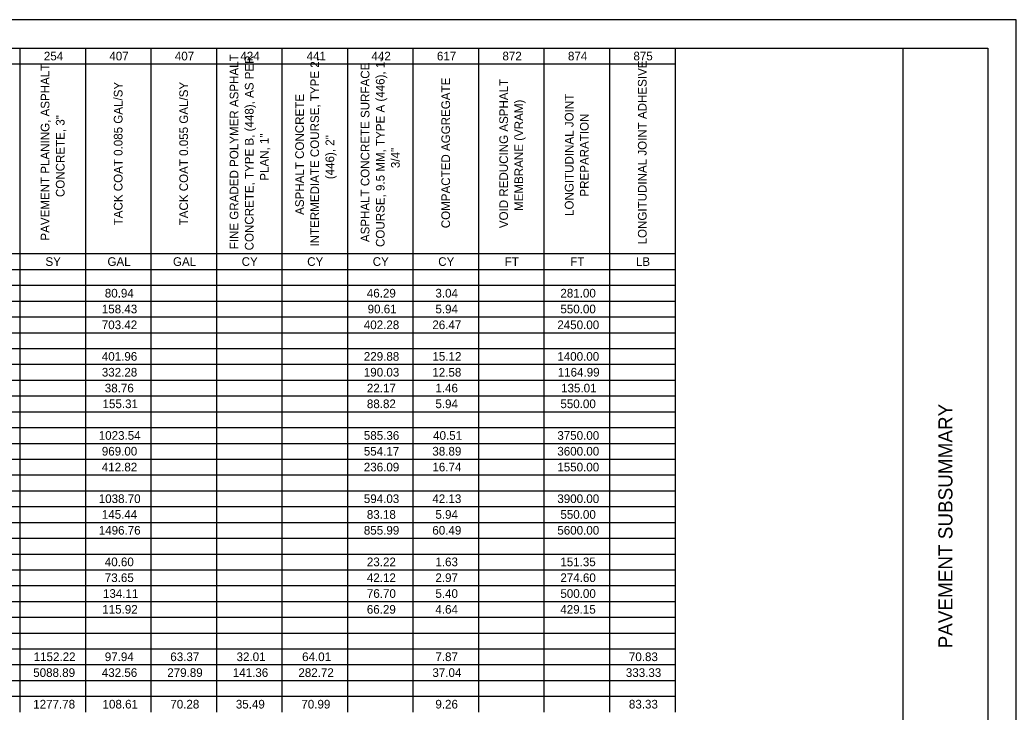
# Model space of a CAD drawing. Extents: x 0 to 34.4, y 0 to 47.
# Drawn here: x 16.38 to 34, y 9.75 to 22 of the extents above; entities that cross this region are included whole.
import ezdxf

# ---------------------------------------------------------------- set-up
doc = ezdxf.new("R2010")
doc.units = 0
for name, color, linetype in [('SH_Border', 7, 'Continuous'), ('SH_Cut_Line', 7, 'Continuous'), ('SH_Data', 7, 'Continuous'), ('SH_Text', 7, 'Continuous')]:
    doc.layers.add(name, color=color, linetype=linetype)

msp = doc.modelspace()

# ---------------------------------------------------------------- linework, layer by layer
at = {"layer": 'SH_Border'}
msp.add_line((32, 0.5), (32, 21.5), dxfattribs=at)
msp.add_lwpolyline([(1.5, 21.5), (33.5, 21.5), (33.5, 0.5), (1.5, 0.5)], close=True, dxfattribs=at)
at = {"layer": 'SH_Cut_Line'}
msp.add_lwpolyline([(0, 0), (34, 0), (34, 22), (0, 22)], close=True, dxfattribs=at)
at = {"layer": 'SH_Text'}
for p, q in [((15.22, 21.5), (16.378, 21.5)), ((16.378, 21.5), (24.49, 21.5)), ((16.378, 21.5), (16.378, 21.22)), ((17.537, 21.5), (17.537, 21.22)), ((18.696, 21.5), (18.696, 21.22)), ((19.855, 21.5), (19.855, 21.22)), ((21.014, 21.5), (21.014, 21.22)), ((22.173, 21.5), (22.173, 21.22)), ((23.331, 21.5), (23.331, 21.22)), ((24.49, 21.5), (25.649, 21.5)), ((24.49, 21.5), (24.49, 21.22)), ((25.649, 21.5), (27.967, 21.5)), ((25.649, 21.5), (25.649, 21.22)), ((26.808, 21.5), (26.808, 21.22)), ((27.967, 21.5), (27.967, 21.22)), ((15.22, 21.22), (16.378, 21.22)), ((16.378, 21.22), (24.49, 21.22)), ((16.378, 21.22), (16.378, 20.941)), ((17.537, 21.22), (17.537, 20.941)), ((18.696, 21.22), (18.696, 20.941)), ((19.855, 21.22), (19.855, 20.941)), ((21.014, 21.22), (21.014, 20.941)), ((22.173, 21.22), (22.173, 20.941)), ((23.331, 21.22), (23.331, 20.941)), ((24.49, 21.22), (25.649, 21.22)), ((24.49, 21.22), (24.49, 20.941)), ((25.649, 21.22), (27.967, 21.22)), ((25.649, 21.22), (25.649, 20.941)), ((26.808, 21.22), (26.808, 20.941)), ((27.967, 21.22), (27.967, 20.941)), ((16.378, 20.941), (16.378, 20.661)), ((17.537, 20.941), (17.537, 20.661)), ((18.696, 20.941), (18.696, 20.661)), ((19.855, 20.941), (19.855, 20.661)), ((21.014, 20.941), (21.014, 20.661)), ((22.173, 20.941), (22.173, 20.661)), ((23.331, 20.941), (23.331, 20.661)), ((24.49, 20.941), (24.49, 20.661)), ((25.649, 20.941), (25.649, 20.661)), ((26.808, 20.941), (26.808, 20.661)), ((27.967, 20.941), (27.967, 20.661)), ((16.378, 20.661), (16.378, 20.101)), ((17.537, 20.661), (17.537, 20.101)), ((18.696, 20.661), (18.696, 20.101)), ((19.855, 20.661), (19.855, 20.101)), ((21.014, 20.661), (21.014, 20.101)), ((22.173, 20.661), (22.173, 20.101)), ((23.331, 20.661), (23.331, 20.101)), ((24.49, 20.661), (24.49, 20.101)), ((25.649, 20.661), (25.649, 20.101)), ((26.808, 20.661), (26.808, 20.101)), ((27.967, 20.661), (27.967, 20.101)), ((16.378, 20.101), (16.378, 19.822)), ((17.537, 20.101), (17.537, 19.822)), ((18.696, 20.101), (18.696, 19.822)), ((19.855, 20.101), (19.855, 19.822)), ((21.014, 20.101), (21.014, 19.822)), ((22.173, 20.101), (22.173, 19.822)), ((23.331, 20.101), (23.331, 19.822)), ((24.49, 20.101), (24.49, 19.822)), ((25.649, 20.101), (25.649, 19.822)), ((26.808, 20.101), (26.808, 19.822)), ((27.967, 20.101), (27.967, 19.822)), ((16.378, 19.822), (16.378, 19.542)), ((17.537, 19.822), (17.537, 19.542)), ((18.696, 19.822), (18.696, 19.542)), ((19.855, 19.822), (19.855, 19.542)), ((21.014, 19.822), (21.014, 19.542)), ((22.173, 19.822), (22.173, 19.542)), ((23.331, 19.822), (23.331, 19.542)), ((24.49, 19.822), (24.49, 19.542)), ((25.649, 19.822), (25.649, 19.542)), ((26.808, 19.822), (26.808, 19.542)), ((27.967, 19.822), (27.967, 19.542)), ((16.378, 19.542), (16.378, 19.262)), ((17.537, 19.542), (17.537, 19.262)), ((18.696, 19.542), (18.696, 19.262)), ((19.855, 19.542), (19.855, 19.262)), ((21.014, 19.542), (21.014, 19.262)), ((22.173, 19.542), (22.173, 19.262)), ((23.331, 19.542), (23.331, 19.262)), ((24.49, 19.542), (24.49, 19.262)), ((25.649, 19.542), (25.649, 19.262)), ((26.808, 19.542), (26.808, 19.262)), ((27.967, 19.542), (27.967, 19.262)), ((16.378, 19.262), (16.378, 18.983)), ((17.537, 19.262), (17.537, 18.983)), ((18.696, 19.262), (18.696, 18.983)), ((19.855, 19.262), (19.855, 18.983)), ((21.014, 19.262), (21.014, 18.983)), ((22.173, 19.262), (22.173, 18.983)), ((23.331, 19.262), (23.331, 18.983)), ((24.49, 19.262), (24.49, 18.983)), ((25.649, 19.262), (25.649, 18.983)), ((26.808, 19.262), (26.808, 18.983)), ((27.967, 19.262), (27.967, 18.983)), ((16.378, 18.983), (16.378, 18.703)), ((17.537, 18.983), (17.537, 18.703)), ((18.696, 18.983), (18.696, 18.703)), ((19.855, 18.983), (19.855, 18.703)), ((21.014, 18.983), (21.014, 18.703)), ((22.173, 18.983), (22.173, 18.703)), ((23.331, 18.983), (23.331, 18.703)), ((24.49, 18.983), (24.49, 18.703)), ((25.649, 18.983), (25.649, 18.703)), ((26.808, 18.983), (26.808, 18.703)), ((27.967, 18.983), (27.967, 18.703)), ((16.378, 18.703), (16.378, 18.423)), ((17.537, 18.703), (17.537, 18.423)), ((18.696, 18.703), (18.696, 18.423)), ((19.855, 18.703), (19.855, 18.423)), ((21.014, 18.703), (21.014, 18.423)), ((22.173, 18.703), (22.173, 18.423)), ((23.331, 18.703), (23.331, 18.423)), ((24.49, 18.703), (24.49, 18.423)), ((25.649, 18.703), (25.649, 18.423)), ((26.808, 18.703), (26.808, 18.423)), ((27.967, 18.703), (27.967, 18.423)), ((16.378, 18.423), (16.378, 18.143)), ((17.537, 18.423), (17.537, 18.143)), ((18.696, 18.423), (18.696, 18.143)), ((19.855, 18.423), (19.855, 18.143)), ((21.014, 18.423), (21.014, 18.143)), ((22.173, 18.423), (22.173, 18.143)), ((23.331, 18.423), (23.331, 18.143)), ((24.49, 18.423), (24.49, 18.143)), ((25.649, 18.423), (25.649, 18.143)), ((26.808, 18.423), (26.808, 18.143)), ((27.967, 18.423), (27.967, 18.143)), ((16.378, 18.143), (16.378, 17.864)), ((17.537, 18.143), (17.537, 17.864)), ((18.696, 18.143), (18.696, 17.864)), ((19.855, 18.143), (19.855, 17.864)), ((21.014, 18.143), (21.014, 17.864)), ((22.173, 18.143), (22.173, 17.864)), ((23.331, 18.143), (23.331, 17.864)), ((24.49, 18.143), (24.49, 17.864)), ((25.649, 18.143), (25.649, 17.864)), ((26.808, 18.143), (26.808, 17.864)), ((27.967, 18.143), (27.967, 17.864)), ((15.22, 17.864), (16.378, 17.864)), ((16.378, 17.864), (24.49, 17.864)), ((16.378, 17.864), (16.378, 17.584)), ((17.537, 17.864), (17.537, 17.584)), ((18.696, 17.864), (18.696, 17.584)), ((19.855, 17.864), (19.855, 17.584)), ((21.014, 17.864), (21.014, 17.584)), ((22.173, 17.864), (22.173, 17.584)), ((23.331, 17.864), (23.331, 17.584)), ((24.49, 17.864), (25.649, 17.864)), ((24.49, 17.864), (24.49, 17.584)), ((25.649, 17.864), (27.967, 17.864)), ((25.649, 17.864), (25.649, 17.584)), ((26.808, 17.864), (26.808, 17.584)), ((27.967, 17.864), (27.967, 17.584)), ((15.22, 17.584), (16.378, 17.584)), ((16.378, 17.584), (24.49, 17.584)), ((16.378, 17.584), (16.378, 17.304)), ((17.537, 17.584), (17.537, 17.304)), ((18.696, 17.584), (18.696, 17.304)), ((19.855, 17.584), (19.855, 17.304)), ((21.014, 17.584), (21.014, 17.304)), ((22.173, 17.584), (22.173, 17.304)), ((23.331, 17.584), (23.331, 17.304)), ((24.49, 17.584), (25.649, 17.584)), ((24.49, 17.584), (24.49, 17.304)), ((25.649, 17.584), (27.967, 17.584)), ((25.649, 17.584), (25.649, 17.304)), ((26.808, 17.584), (26.808, 17.304)), ((27.967, 17.584), (27.967, 17.304)), ((15.22, 17.304), (16.378, 17.304)), ((16.378, 17.304), (24.49, 17.304)), ((16.378, 17.304), (16.378, 17.024)), ((17.537, 17.304), (17.537, 17.024)), ((18.696, 17.304), (18.696, 17.024)), ((19.855, 17.304), (19.855, 17.024)), ((21.014, 17.304), (21.014, 17.024)), ((22.173, 17.304), (22.173, 17.024)), ((23.331, 17.304), (23.331, 17.024)), ((24.49, 17.304), (25.649, 17.304)), ((24.49, 17.304), (24.49, 17.024)), ((25.649, 17.304), (27.967, 17.304)), ((25.649, 17.304), (25.649, 17.024)), ((26.808, 17.304), (26.808, 17.024)), ((27.967, 17.304), (27.967, 17.024)), ((15.22, 17.024), (16.378, 17.024)), ((16.378, 17.024), (24.49, 17.024)), ((16.378, 17.024), (16.378, 16.745)), ((17.537, 17.024), (17.537, 16.745)), ((18.696, 17.024), (18.696, 16.745)), ((19.855, 17.024), (19.855, 16.745)), ((21.014, 17.024), (21.014, 16.745)), ((22.173, 17.024), (22.173, 16.745)), ((23.331, 17.024), (23.331, 16.745)), ((24.49, 17.024), (25.649, 17.024)), ((24.49, 17.024), (24.49, 16.745)), ((25.649, 17.024), (27.967, 17.024)), ((25.649, 17.024), (25.649, 16.745)), ((26.808, 17.024), (26.808, 16.745)), ((27.967, 17.024), (27.967, 16.745)), ((15.22, 16.745), (16.378, 16.745)), ((16.378, 16.745), (24.49, 16.745)), ((16.378, 16.745), (16.378, 16.185)), ((17.537, 16.745), (17.537, 16.185)), ((18.696, 16.745), (18.696, 16.185)), ((19.855, 16.745), (19.855, 16.185)), ((21.014, 16.745), (21.014, 16.185)), ((22.173, 16.745), (22.173, 16.185)), ((23.331, 16.745), (23.331, 16.185)), ((24.49, 16.745), (25.649, 16.745)), ((24.49, 16.745), (24.49, 16.185)), ((25.649, 16.745), (27.967, 16.745)), ((25.649, 16.745), (25.649, 16.185)), ((26.808, 16.745), (26.808, 16.185)), ((27.967, 16.745), (27.967, 16.185)), ((15.22, 16.465), (16.378, 16.465)), ((16.378, 16.465), (24.49, 16.465)), ((24.49, 16.465), (25.649, 16.465)), ((25.649, 16.465), (27.967, 16.465)), ((15.22, 16.185), (16.378, 16.185)), ((16.378, 16.185), (24.49, 16.185)), ((16.378, 16.185), (16.378, 15.906)), ((17.537, 16.185), (17.537, 15.906)), ((18.696, 16.185), (18.696, 15.906)), ((19.855, 16.185), (19.855, 15.906)), ((21.014, 16.185), (21.014, 15.906)), ((22.173, 16.185), (22.173, 15.906)), ((23.331, 16.185), (23.331, 15.906)), ((24.49, 16.185), (25.649, 16.185)), ((24.49, 16.185), (24.49, 15.906)), ((25.649, 16.185), (27.967, 16.185)), ((25.649, 16.185), (25.649, 15.906)), ((26.808, 16.185), (26.808, 15.906)), ((27.967, 16.185), (27.967, 15.906)), ((15.22, 15.906), (16.378, 15.906)), ((16.378, 15.906), (24.49, 15.906)), ((16.378, 15.906), (16.378, 15.626)), ((17.537, 15.906), (17.537, 15.626)), ((18.696, 15.906), (18.696, 15.626)), ((19.855, 15.906), (19.855, 15.626)), ((21.014, 15.906), (21.014, 15.626)), ((22.173, 15.906), (22.173, 15.626)), ((23.331, 15.906), (23.331, 15.626)), ((24.49, 15.906), (25.649, 15.906)), ((24.49, 15.906), (24.49, 15.626)), ((25.649, 15.906), (27.967, 15.906)), ((25.649, 15.906), (25.649, 15.626)), ((26.808, 15.906), (26.808, 15.626)), ((27.967, 15.906), (27.967, 15.626)), ((15.22, 15.626), (16.378, 15.626)), ((16.378, 15.626), (24.49, 15.626)), ((16.378, 15.626), (16.378, 15.346)), ((17.537, 15.626), (17.537, 15.346)), ((18.696, 15.626), (18.696, 15.346)), ((19.855, 15.626), (19.855, 15.346)), ((21.014, 15.626), (21.014, 15.346)), ((22.173, 15.626), (22.173, 15.346)), ((23.331, 15.626), (23.331, 15.346)), ((24.49, 15.626), (25.649, 15.626)), ((24.49, 15.626), (24.49, 15.346)), ((25.649, 15.626), (27.967, 15.626)), ((25.649, 15.626), (25.649, 15.346)), ((26.808, 15.626), (26.808, 15.346)), ((27.967, 15.626), (27.967, 15.346)), ((15.22, 15.346), (16.378, 15.346)), ((16.378, 15.346), (24.49, 15.346)), ((16.378, 15.346), (16.378, 14.787)), ((17.537, 15.346), (17.537, 14.787)), ((18.696, 15.346), (18.696, 14.787)), ((19.855, 15.346), (19.855, 14.787)), ((21.014, 15.346), (21.014, 14.787)), ((22.173, 15.346), (22.173, 14.787)), ((23.331, 15.346), (23.331, 14.787)), ((24.49, 15.346), (25.649, 15.346)), ((24.49, 15.346), (24.49, 14.787)), ((25.649, 15.346), (27.967, 15.346)), ((25.649, 15.346), (25.649, 14.787)), ((26.808, 15.346), (26.808, 14.787)), ((27.967, 15.346), (27.967, 14.787)), ((15.22, 15.066), (16.378, 15.066)), ((16.378, 15.066), (24.49, 15.066)), ((24.49, 15.066), (25.649, 15.066)), ((25.649, 15.066), (27.967, 15.066)), ((15.22, 14.787), (16.378, 14.787)), ((16.378, 14.787), (24.49, 14.787)), ((16.378, 14.787), (16.378, 14.507)), ((17.537, 14.787), (17.537, 14.507)), ((18.696, 14.787), (18.696, 14.507)), ((19.855, 14.787), (19.855, 14.507)), ((21.014, 14.787), (21.014, 14.507)), ((22.173, 14.787), (22.173, 14.507)), ((23.331, 14.787), (23.331, 14.507)), ((24.49, 14.787), (25.649, 14.787)), ((24.49, 14.787), (24.49, 14.507)), ((25.649, 14.787), (27.967, 14.787)), ((25.649, 14.787), (25.649, 14.507)), ((26.808, 14.787), (26.808, 14.507)), ((27.967, 14.787), (27.967, 14.507)), ((15.22, 14.507), (16.378, 14.507)), ((16.378, 14.507), (24.49, 14.507)), ((16.378, 14.507), (16.378, 14.227)), ((17.537, 14.507), (17.537, 14.227)), ((18.696, 14.507), (18.696, 14.227)), ((19.855, 14.507), (19.855, 14.227)), ((21.014, 14.507), (21.014, 14.227)), ((22.173, 14.507), (22.173, 14.227)), ((23.331, 14.507), (23.331, 14.227)), ((24.49, 14.507), (25.649, 14.507)), ((24.49, 14.507), (24.49, 14.227)), ((25.649, 14.507), (27.967, 14.507)), ((25.649, 14.507), (25.649, 14.227)), ((26.808, 14.507), (26.808, 14.227)), ((27.967, 14.507), (27.967, 14.227)), ((15.22, 14.227), (16.378, 14.227)), ((16.378, 14.227), (24.49, 14.227)), ((16.378, 14.227), (16.378, 13.948)), ((17.537, 14.227), (17.537, 13.948)), ((18.696, 14.227), (18.696, 13.948)), ((19.855, 14.227), (19.855, 13.948)), ((21.014, 14.227), (21.014, 13.948)), ((22.173, 14.227), (22.173, 13.948)), ((23.331, 14.227), (23.331, 13.948)), ((24.49, 14.227), (25.649, 14.227)), ((24.49, 14.227), (24.49, 13.948)), ((25.649, 14.227), (27.967, 14.227)), ((25.649, 14.227), (25.649, 13.948)), ((26.808, 14.227), (26.808, 13.948)), ((27.967, 14.227), (27.967, 13.948)), ((15.22, 13.948), (16.378, 13.948)), ((16.378, 13.948), (24.49, 13.948)), ((16.378, 13.948), (16.378, 13.108)), ((17.537, 13.948), (17.537, 13.108)), ((18.696, 13.948), (18.696, 13.108)), ((19.855, 13.948), (19.855, 13.108)), ((21.014, 13.948), (21.014, 13.108)), ((22.173, 13.948), (22.173, 13.108)), ((23.331, 13.948), (23.331, 13.108)), ((24.49, 13.948), (25.649, 13.948)), ((24.49, 13.948), (24.49, 13.108)), ((25.649, 13.948), (27.967, 13.948)), ((25.649, 13.948), (25.649, 13.108)), ((26.808, 13.948), (26.808, 13.108)), ((27.967, 13.948), (27.967, 13.108)), ((15.22, 13.668), (16.378, 13.668)), ((16.378, 13.668), (24.49, 13.668)), ((24.49, 13.668), (25.649, 13.668)), ((25.649, 13.668), (27.967, 13.668)), ((15.22, 13.388), (16.378, 13.388)), ((16.378, 13.388), (24.49, 13.388)), ((24.49, 13.388), (25.649, 13.388)), ((25.649, 13.388), (27.967, 13.388)), ((15.22, 13.108), (16.378, 13.108)), ((16.378, 13.108), (24.49, 13.108)), ((16.378, 13.108), (16.378, 12.829)), ((17.537, 13.108), (17.537, 12.829)), ((18.696, 13.108), (18.696, 12.829)), ((19.855, 13.108), (19.855, 12.829)), ((21.014, 13.108), (21.014, 12.829)), ((22.173, 13.108), (22.173, 12.829)), ((23.331, 13.108), (23.331, 12.829)), ((24.49, 13.108), (25.649, 13.108)), ((24.49, 13.108), (24.49, 12.829)), ((25.649, 13.108), (27.967, 13.108)), ((25.649, 13.108), (25.649, 12.829)), ((26.808, 13.108), (26.808, 12.829)), ((27.967, 13.108), (27.967, 12.829)), ((15.22, 12.829), (16.378, 12.829)), ((16.378, 12.829), (24.49, 12.829)), ((16.378, 12.829), (16.378, 11.71)), ((17.537, 12.829), (17.537, 11.71)), ((18.696, 12.829), (18.696, 11.71)), ((19.855, 12.829), (19.855, 11.71)), ((21.014, 12.829), (21.014, 11.71)), ((22.173, 12.829), (22.173, 11.71)), ((23.331, 12.829), (23.331, 11.71)), ((24.49, 12.829), (25.649, 12.829)), ((24.49, 12.829), (24.49, 11.71)), ((25.649, 12.829), (27.967, 12.829)), ((25.649, 12.829), (25.649, 11.71)), ((26.808, 12.829), (26.808, 11.71)), ((27.967, 12.829), (27.967, 11.71)), ((15.22, 12.549), (16.378, 12.549)), ((16.378, 12.549), (24.49, 12.549)), ((24.49, 12.549), (25.649, 12.549)), ((25.649, 12.549), (27.967, 12.549)), ((15.22, 12.269), (16.378, 12.269)), ((16.378, 12.269), (24.49, 12.269)), ((24.49, 12.269), (25.649, 12.269)), ((25.649, 12.269), (27.967, 12.269)), ((15.22, 11.99), (16.378, 11.99)), ((16.378, 11.99), (24.49, 11.99)), ((24.49, 11.99), (25.649, 11.99)), ((25.649, 11.99), (27.967, 11.99)), ((15.22, 11.71), (16.378, 11.71)), ((16.378, 11.71), (24.49, 11.71)), ((16.378, 11.71), (16.378, 11.43)), ((17.537, 11.71), (17.537, 11.43)), ((18.696, 11.71), (18.696, 11.43)), ((19.855, 11.71), (19.855, 11.43)), ((21.014, 11.71), (21.014, 11.43)), ((22.173, 11.71), (22.173, 11.43)), ((23.331, 11.71), (23.331, 11.43)), ((24.49, 11.71), (25.649, 11.71)), ((24.49, 11.71), (24.49, 11.43)), ((25.649, 11.71), (27.967, 11.71)), ((25.649, 11.71), (25.649, 11.43)), ((26.808, 11.71), (26.808, 11.43)), ((27.967, 11.71), (27.967, 11.43)), ((15.22, 11.43), (16.378, 11.43)), ((16.378, 11.43), (24.49, 11.43)), ((16.378, 11.43), (16.378, 10.311)), ((17.537, 11.43), (17.537, 10.311)), ((18.696, 11.43), (18.696, 10.311)), ((19.855, 11.43), (19.855, 10.311)), ((21.014, 11.43), (21.014, 10.311)), ((22.173, 11.43), (22.173, 10.311)), ((23.331, 11.43), (23.331, 10.311)), ((24.49, 11.43), (25.649, 11.43)), ((24.49, 11.43), (24.49, 10.311)), ((25.649, 11.43), (27.967, 11.43)), ((25.649, 11.43), (25.649, 10.311)), ((26.808, 11.43), (26.808, 10.311)), ((27.967, 11.43), (27.967, 10.311)), ((15.22, 11.15), (16.378, 11.15)), ((16.378, 11.15), (24.49, 11.15)), ((24.49, 11.15), (25.649, 11.15)), ((25.649, 11.15), (27.967, 11.15)), ((15.22, 10.871), (16.378, 10.871)), ((16.378, 10.871), (24.49, 10.871)), ((24.49, 10.871), (25.649, 10.871)), ((25.649, 10.871), (27.967, 10.871)), ((15.22, 10.591), (16.378, 10.591)), ((16.378, 10.591), (24.49, 10.591)), ((24.49, 10.591), (25.649, 10.591)), ((25.649, 10.591), (27.967, 10.591)), ((15.22, 10.311), (16.378, 10.311)), ((16.378, 10.311), (24.49, 10.311)), ((16.378, 10.311), (16.378, 9.752)), ((17.537, 10.311), (17.537, 9.752)), ((18.696, 10.311), (18.696, 9.752)), ((19.855, 10.311), (19.855, 9.752)), ((21.014, 10.311), (21.014, 9.752)), ((22.173, 10.311), (22.173, 9.752)), ((23.331, 10.311), (23.331, 9.752)), ((24.49, 10.311), (25.649, 10.311)), ((24.49, 10.311), (24.49, 9.752)), ((25.649, 10.311), (27.967, 10.311)), ((25.649, 10.311), (25.649, 9.752)), ((26.808, 10.311), (26.808, 9.752)), ((27.967, 10.311), (27.967, 9.752)), ((15.22, 10.031), (16.378, 10.031)), ((16.378, 10.031), (24.49, 10.031)), ((24.49, 10.031), (25.649, 10.031)), ((25.649, 10.031), (27.967, 10.031))]:
    msp.add_line(p, q, dxfattribs=at)

# ---------------------------------------------------------------- texts
at = {"layer": 'SH_Data'}
msp.add_text('PAVEMENT SUBSUMMARY', height=0.25, rotation=90, dxfattribs=at).set_placement((32.875, 10.879))
at = {"layer": 'SH_Text'}
for s, p in [('254', (16.802, 21.284)), ('407', (17.96, 21.284)), ('407', (19.119, 21.284)), ('424', (20.278, 21.284)), ('441', (21.45, 21.284)), ('442', (22.597, 21.284)), ('617', (23.755, 21.284)), ('872', (24.914, 21.284)), ('874', (26.073, 21.284)), ('875', (27.231, 21.284)), ('SY', (16.83, 17.647)), ('GAL', (17.927, 17.647)), ('GAL', (19.086, 17.647)), ('CY', (20.301, 17.647)), ('CY', (21.46, 17.647)), ('CY', (22.619, 17.647)), ('CY', (23.778, 17.647)), ('FT', (24.954, 17.647)), ('FT', (26.113, 17.647)), ('LB', (27.275, 17.647)), ('80.94', (17.88, 17.088)), ('46.29', (22.515, 17.088)), ('3.04', (23.728, 17.088)), ('281.00', (25.939, 17.088)), ('158.43', (17.827, 16.808)), ('90.61', (22.529, 16.808)), ('5.94', (23.728, 16.808)), ('550.00', (25.939, 16.808)), ('703.42', (17.827, 16.528)), ('402.28', (22.462, 16.528)), ('26.47', (23.674, 16.528)), ('2450.00', (25.885, 16.528)), ('401.96', (17.827, 15.969)), ('229.88', (22.462, 15.969)), ('15.12', (23.675, 15.969)), ('1400.00', (25.885, 15.969)), ('332.28', (17.827, 15.689)), ('190.03', (22.462, 15.689)), ('12.58', (23.674, 15.689)), ('1164.99', (25.892, 15.689)), ('38.76', (17.88, 15.409)), ('22.17', (22.516, 15.409)), ('1.46', (23.728, 15.409)), ('135.01', (25.952, 15.409)), ('155.31', (17.84, 15.13)), ('88.82', (22.516, 15.13)), ('5.94', (23.728, 15.13)), ('550.00', (25.939, 15.13)), ('1023.54', (17.773, 14.57)), ('585.36', (22.462, 14.57)), ('40.51', (23.688, 14.57)), ('3750.00', (25.885, 14.57)), ('969.00', (17.827, 14.291)), ('554.17', (22.462, 14.291)), ('38.89', (23.674, 14.291)), ('3600.00', (25.885, 14.291)), ('412.82', (17.827, 14.011)), ('236.09', (22.462, 14.011)), ('16.74', (23.675, 14.011)), ('1550.00', (25.885, 14.011)), ('1038.70', (17.773, 13.451)), ('594.03', (22.462, 13.451)), ('42.13', (23.674, 13.451)), ('3900.00', (25.885, 13.451)), ('145.44', (17.827, 13.172)), ('83.18', (22.515, 13.172)), ('5.94', (23.728, 13.172)), ('550.00', (25.939, 13.172)), ('1496.76', (17.773, 12.892)), ('855.99', (22.462, 12.892)), ('60.49', (23.674, 12.892)), ('5600.00', (25.885, 12.892)), ('40.60', (17.88, 12.333)), ('23.22', (22.516, 12.333)), ('1.63', (23.728, 12.333)), ('151.35', (25.938, 12.333)), ('73.65', (17.88, 12.053)), ('42.12', (22.516, 12.053)), ('2.97', (23.728, 12.053)), ('274.60', (25.939, 12.053)), ('134.11', (17.847, 11.773)), ('76.70', (22.516, 11.773)), ('5.40', (23.728, 11.773)), ('500.00', (25.939, 11.773)), ('115.92', (17.835, 11.493)), ('66.29', (22.515, 11.493)), ('4.64', (23.728, 11.493)), ('429.15', (25.938, 11.493)), ('1152.22', (16.622, 10.654)), ('97.94', (17.88, 10.654)), ('63.37', (19.039, 10.654)), ('32.01', (20.211, 10.654)), ('64.01', (21.37, 10.654)), ('7.87', (23.728, 10.654)), ('70.83', (27.151, 10.654)), ('5088.89', (16.614, 10.374)), ('432.56', (17.827, 10.374)), ('279.89', (18.985, 10.374)), ('141.36', (20.144, 10.374)), ('282.72', (21.304, 10.374)), ('37.04', (23.675, 10.374)), ('333.33', (27.097, 10.374)), ('1277.78', (16.614, 9.815)), ('108.61', (17.84, 9.815)), ('70.28', (19.039, 9.815)), ('35.49', (20.198, 9.815)), ('70.99', (21.357, 9.815)), ('9.26', (23.728, 9.815)), ('83.33', (27.151, 9.815))]:
    msp.add_text(s, height=0.1532, dxfattribs=at).set_placement(p)
for s, height, p in [('FINE GRADED POLYMER ASPHALT ', 0.15318, (20.243, 17.942)), ('CONCRETE, TYPE B, (448), AS PER ', 0.15318, (20.511, 17.922)), ('PAVEMENT PLANING, ASPHALT ', 0.15318, (16.9, 18.095)), ('INTERMEDIATE COURSE, TYPE 2, ', 0.15318, (21.67, 17.99)), ('ASPHALT CONCRETE SURFACE ', 0.15318, (22.561, 18.068)), ('COURSE, 9.5 MM, TYPE A (446), 1-', 0.15318, (22.829, 17.982)), ('LONGITUDINAL JOINT ADHESIVE', 0.15318, (27.464, 18.027)), ('TACK COAT 0.085 GAL/SY', 0.15318, (18.193, 18.365)), ('TACK COAT 0.055 GAL/SY', 0.15318, (19.352, 18.365)), ('COMPACTED AGGREGATE', 0.15318, (23.987, 18.314)), ('VOID REDUCING ASPHALT ', 0.15318, (25.012, 18.315)), ('ASPHALT CONCRETE ', 0.15318, (21.402, 18.55)), ('LONGITUDINAL JOINT ', 0.15318, (26.171, 18.531)), ('MEMBRANE (VRAM)', 0.15318, (25.28, 18.62)), ('CONCRETE, 3"', 0.15318, (17.168, 18.865)), ('PREPARATION', 0.15318, (26.439, 18.874)), ('PLAN, 1"', 0.1532, (20.779, 19.154)), ('(446), 2"', 0.1532, (21.938, 19.181)), ('3/4"', 0.1532, (23.097, 19.378))]:
    msp.add_text(s, height=height, rotation=90, dxfattribs=at).set_placement(p)

doc.saveas('drawing.dxf')
